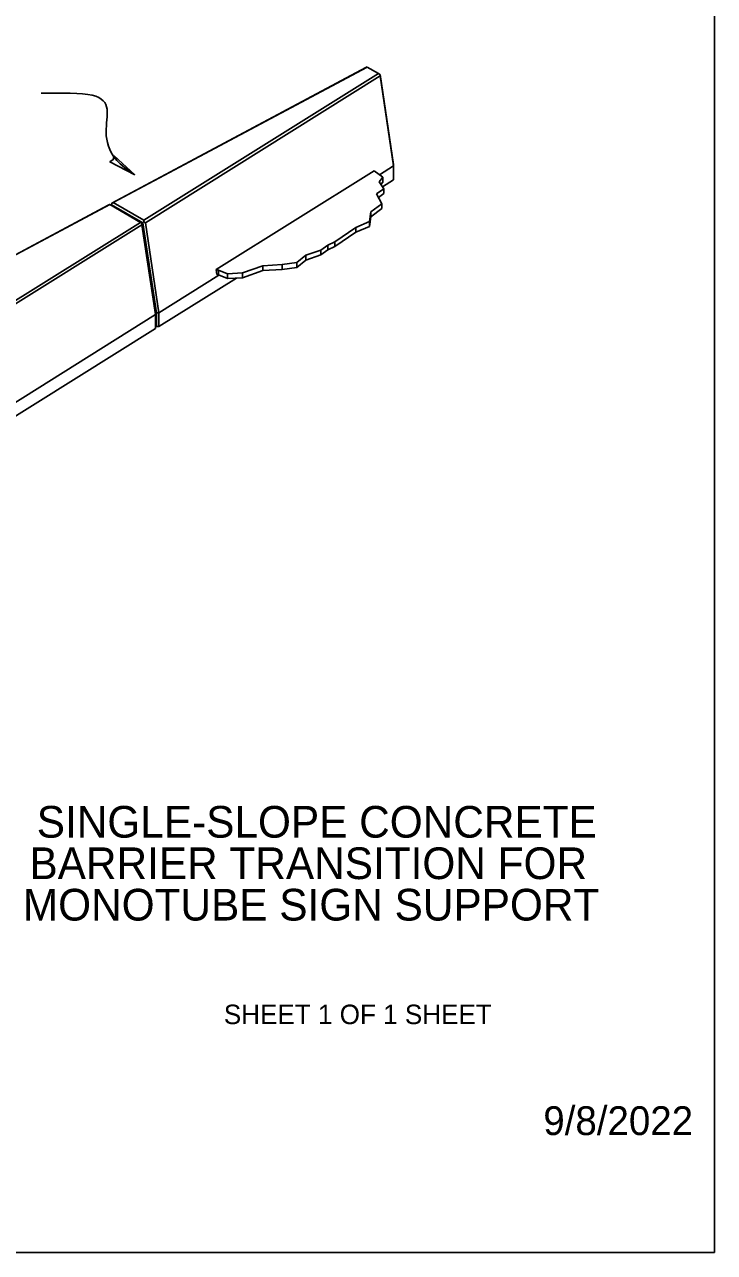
# Model space of a CAD drawing. Extents: x 99862 to 103151, y 100000 to 102076.
# Drawn here: x 102585 to 103151, y 100000 to 101007 of the extents above; entities that cross this region are included whole.
import ezdxf

# ---------------------------------------------------------------- set-up
doc = ezdxf.new("R2010")
doc.units = 0
for name, color, linetype in [('Level 1', 7, 'Continuous'), ('Level 15', 7, 'Continuous'), ('Level 2', 7, 'Continuous'), ('Level 3', 7, 'Continuous'), ('Level 62', 7, 'Continuous'), ('Level 8', 7, 'Continuous')]:
    doc.layers.add(name, color=color, linetype=linetype)

msp = doc.modelspace()

# ---------------------------------------------------------------- linework, layer by layer
at = {"layer": 'Level 1'}
msp.add_lwpolyline([(99862, 99999.5), (103151, 99999.5), (103151, 102075.5), (99862, 102075.5)], close=True, dxfattribs=at)
at = {"layer": 'Level 15'}
for q in [(102598.1, 100950.5), (102622, 100950.5)]:
    msp.add_line((102614, 100950.5), q, dxfattribs=at)
msp.add_lwpolyline([(102675.2, 100883.7), (102654.7, 100894.2), (102657.3, 100896.1), (102658.1, 100899.1)], close=True, dxfattribs=at)
msp.add_open_spline([(102675.2, 100883.7), (102622.4, 100914.7), (102684.4, 100950.5), (102622, 100950.5)], degree=3, dxfattribs=at)
at = {"layer": 'Level 2'}
for p, q in [((102864.7, 100971.6), (102656.2, 100860.3)), ((102657.4, 100860.8), (102866, 100972)), ((102864.7, 100971.6), (102865.9, 100972.1)), ((102865.9, 100972.1), (102866, 100972)), ((102866, 100972), (102875.2, 100966.7)), ((102875.2, 100966.7), (102876.4, 100966)), ((102876.4, 100966), (102876.5, 100964.8)), ((102876.5, 100966), (102876.4, 100966)), ((102887.6, 100892.1), (102876.5, 100966)), ((102876.5, 100964.8), (102887.6, 100891)), ((102887.6, 100891), (102876, 100883.7)), ((102887.6, 100892.1), (102887.6, 100891)), ((102887.6, 100891), (102887.6, 100879.5)), ((102887.6, 100891), (102887.6, 100891)), ((102887.6, 100879.5), (102878.4, 100873.8)), ((102445.7, 100747.8), (102654.5, 100859.2)), ((102653.3, 100858.7), (102654.4, 100859.2)), ((102654.4, 100859.2), (102655.4, 100858.7)), ((102655.4, 100858.7), (102655.9, 100858.9)), ((102655.9, 100858.9), (102656.2, 100860.3)), ((102653.3, 100858.7), (102444.5, 100747.3)), ((102744.2, 100801.4), (102694.9, 100770.5)), ((102758.6, 100798.9), (102694.9, 100759.1)), ((102692.1, 100768.9), (102499.3, 100648.3)), ((102692.1, 100770), (102692.8, 100770.4)), ((102692.1, 100768.9), (102692.1, 100770)), ((102692.8, 100770.4), (102694.9, 100770.5)), ((102692.1, 100758.7), (102692.8, 100759.1)), ((102692.1, 100757.4), (102692.1, 100758.7)), ((102692.8, 100759.1), (102694.9, 100759.1)), ((102499.3, 100636.9), (102692.1, 100757.4))]:
    msp.add_line(p, q, dxfattribs=at)
at = {"layer": 'Level 3'}
for p, q in [((102875.2, 100966.7), (102682.5, 100846.3)), ((102683.8, 100844.3), (102876.5, 100964.8)), ((102654.4, 100859.2), (102653.3, 100858.7)), ((102654.5, 100859.2), (102654.4, 100859.2)), ((102654.5, 100859.2), (102679.7, 100844.6)), ((102655.4, 100858.7), (102656.1, 100859)), ((102656.2, 100860.3), (102655.9, 100858.9)), ((102656.2, 100860.2), (102656.1, 100859)), ((102681.7, 100844.3), (102656.1, 100859)), ((102656.1, 100859), (102656.1, 100859)), ((102656.1, 100859), (102656.1, 100859)), ((102656.2, 100860.2), (102657.4, 100860.8)), ((102656.2, 100860.3), (102656.2, 100860.2)), ((102682.5, 100846.3), (102657.4, 100860.8)), ((102679.7, 100844.6), (102486.9, 100724.1)), ((102488.1, 100722.1), (102681, 100842.7)), ((102680.9, 100843.9), (102679.7, 100844.6)), ((102681, 100842.7), (102680.9, 100843.9)), ((102681, 100843.9), (102680.9, 100843.9)), ((102681.7, 100844.3), (102681, 100843.9)), ((102692.1, 100770), (102681, 100843.9)), ((102681, 100842.7), (102692.1, 100768.9)), ((102682.6, 100845), (102681.7, 100844.3)), ((102681.7, 100844.3), (102681.7, 100844.3)), ((102681.7, 100844.3), (102692.8, 100770.4)), ((102692.8, 100770.4), (102681.7, 100844.3)), ((102682.5, 100846.3), (102682.6, 100845)), ((102682.6, 100845), (102683.8, 100844.3)), ((102694.9, 100770.5), (102683.8, 100844.3)), ((102692.8, 100770.4), (102692.1, 100770)), ((102692.1, 100770), (102692.1, 100768.9)), ((102692.1, 100768.9), (102692.1, 100757.4)), ((102692.1, 100768.9), (102692.1, 100768.9)), ((102694.9, 100770.5), (102692.8, 100770.4)), ((102692.8, 100770.4), (102692.8, 100759.1)), ((102692.8, 100770.4), (102692.8, 100759.1)), ((102694.9, 100770.5), (102694.9, 100770.5)), ((102694.9, 100759.1), (102694.9, 100770.5)), ((102692.1, 100758.7), (102692.8, 100759.1)), ((102692.8, 100759.1), (102692.8, 100759.1)), ((102692.8, 100759.1), (102694.9, 100759.1))]:
    msp.add_line(p, q, dxfattribs=at)
at = {"layer": 'Level 8'}
for p, q in [((102871.6, 100886.9), (102741.8, 100805.8)), ((102878.7, 100881.6), (102871.6, 100886.9)), ((102875.8, 100877.8), (102878.7, 100881.6)), ((102878.7, 100877.7), (102878.7, 100881.6)), ((102873.6, 100867.9), (102879.5, 100872.2)), ((102879.5, 100872.2), (102875.8, 100877.8)), ((102877.2, 100875.7), (102878.7, 100877.7)), ((102879.5, 100868.3), (102879.5, 100872.2)), ((102868.8, 100853.1), (102878, 100859.8)), ((102878, 100859.8), (102873.6, 100867.9)), ((102875.1, 100865.1), (102879.5, 100868.3)), ((102878, 100855.9), (102878, 100859.8)), ((102867.7, 100845.2), (102868.8, 100853.1)), ((102867.7, 100841.3), (102868.8, 100849.2)), ((102868.8, 100849.2), (102878, 100855.9)), ((102868.8, 100849.2), (102868.8, 100853.1)), ((102839.4, 100828.7), (102856.6, 100840.5)), ((102856.6, 100840.5), (102867.7, 100845.2)), ((102856.6, 100836.6), (102867.7, 100841.3)), ((102856.6, 100836.6), (102856.6, 100840.5)), ((102867.7, 100841.3), (102867.7, 100845.2)), ((102833.6, 100826), (102839.4, 100828.7)), ((102839.4, 100824.8), (102856.6, 100836.6)), ((102839.4, 100828.7), (102839.4, 100824.8)), ((102815.4, 100817.6), (102827.7, 100821.8)), ((102827.7, 100821.8), (102833.6, 100826)), ((102827.7, 100817.9), (102833.6, 100822)), ((102827.7, 100817.9), (102827.7, 100821.8)), ((102833.6, 100822), (102833.6, 100826)), ((102833.6, 100822), (102839.4, 100824.8)), ((102763.5, 100803.1), (102780.1, 100808.9)), ((102780.1, 100808.9), (102796.1, 100809.9)), ((102780.1, 100805), (102780.1, 100808.9)), ((102796.1, 100809.9), (102808, 100811.6)), ((102796.1, 100806), (102796.1, 100809.9)), ((102808, 100811.6), (102815.4, 100817.6)), ((102808, 100807.7), (102815.4, 100813.7)), ((102808, 100807.7), (102808, 100811.6)), ((102815.4, 100813.7), (102827.7, 100817.9)), ((102815.4, 100813.7), (102815.4, 100817.6)), ((102741.8, 100805.8), (102743.8, 100805.4)), ((102741.8, 100805.8), (102742.4, 100801.8)), ((102742.4, 100801.8), (102743.8, 100801.5)), ((102743.8, 100805.4), (102751.2, 100802.4)), ((102743.8, 100801.5), (102743.8, 100805.4)), ((102743.8, 100801.5), (102751.2, 100798.5)), ((102751.2, 100802.4), (102763.5, 100803.1)), ((102751.2, 100798.5), (102751.2, 100802.4)), ((102751.2, 100798.5), (102763.5, 100799.2)), ((102763.5, 100799.2), (102780.1, 100805)), ((102763.5, 100799.2), (102763.5, 100803.1)), ((102780.1, 100805), (102796.1, 100806)), ((102796.1, 100806), (102808, 100807.7))]:
    msp.add_line(p, q, dxfattribs=at)

# ---------------------------------------------------------------- texts
at = {"layer": 'Level 15'}
msp.add_text('9/8/2022', height=23.62, dxfattribs=at).set_placement((103010.5, 100095.8))
at = {"layer": 'Level 62'}
for s, height, p in [('SINGLE-SLOPE CONCRETE', 26, (102594.6, 100339.8)), ('BARRIER TRANSITION FOR', 26, (102588.6, 100305.8)), ('MONOTUBE SIGN SUPPORT', 26, (102583.2, 100271.8)), ('SHEET 1 OF 1 SHEET', 16, (102748.2, 100186.8))]:
    msp.add_text(s, height=height, dxfattribs=at).set_placement(p)

doc.saveas('drawing.dxf')
